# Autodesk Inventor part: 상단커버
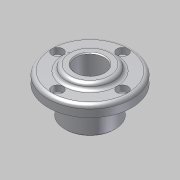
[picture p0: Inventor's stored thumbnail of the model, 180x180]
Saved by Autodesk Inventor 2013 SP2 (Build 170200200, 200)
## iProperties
Created: 2014-03
Part Number: 상단커버
Document SubType Name: Modeling
Designer: SeoGD™[esajin.kr]
Density: 1 g/cm^3
Material: 일반
Author: SeoGD™[esajin.kr]
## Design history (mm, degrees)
sketch "스케치1"
  geometry: C1 r 22.5 at (0, 0) reference; C2 r 13.5 at (0, 0) reference; 1 further point
  node "참조1"
  node "참조2"
extrude "돌출1" new body sketch "스케치1" distance "d0" = 6; taper "d1" = 0 deg
extrude "돌출2" join sketch "스케치1" distance "d2" = 15; taper "d3" = 0 deg
sketch "스케치2"
  geometry: C1 r 7.5 at (0, 0); 1 further point
  constraints: 1 centre point, 1 coincident
  dimensions: "d4" = 15 diameter of C1
extrude "돌출3" cut sketch "스케치2" stored distance "d5" = 15; taper "d6" = 0 deg
sketch "스케치3"
  geometry: C1 r 7.5 at (0, 0) reference; C2 r 1.23 at (0, 17.5) reference; C3 r 12.5 at (0, 0); 1 further point
  constraints: 1 centre point, 1 coincident
  dimensions: "d7" = 25 diameter of C3
  node "참조3"
extrude "돌출4" join sketch "스케치3" distance "d8" = 3; taper "d9" = 0 deg
hole "구멍1" sketch "스케치3" diameter "d10" = 3.4; stored, may be unused: countersink angle "d14" = 90 deg, drill point angle "d16" = 118 deg; dims "d11" = 6, "d12" = 6, "d13" = 3.3, "d15" = 8
fillet "모깎기1" dims "d20" = 2
chamfer "모따기1" distance "d21" = 0.5; stored, may be unused: second distance "d22" = 2, angle "d23" = 45 deg
node "솔리드1"
pattern_circular "원형 패턴1" dims angle "d18" = 360 deg
